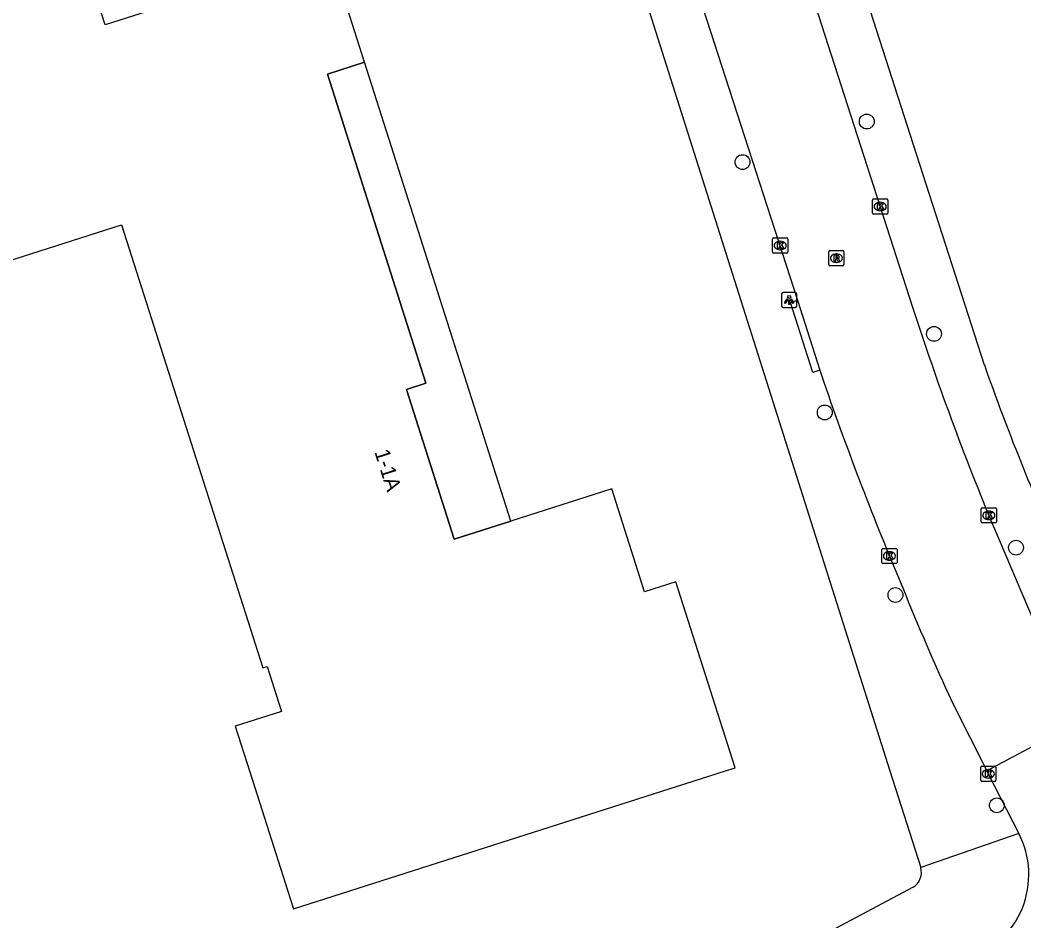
# Model space of a CAD drawing. Extents: x 159503 to 160347, y 382525 to 383272.
# Drawn here: x 159706.3 to 159772.6, y 382740.1 to 382799.5 of the extents above; entities that cross this region are included whole.
import ezdxf

# ---------------------------------------------------------------- set-up
doc = ezdxf.new("R2010")
doc.units = 0
for name, color, linetype in [('IMGEO_Boom', 7, 'Continuous'), ('IMGEO_Kolk', 7, 'Continuous'), ('IMGEO_Lichtpunt', 7, 'Continuous'), ('IMGEO_Pand', 7, 'Continuous'), ('IMGEO_Pand_nummerreeks', 7, 'Continuous'), ('IMGEO_Pand_overbouw', 7, 'Continuous'), ('IMGEO_Rijbaan_lokaal_open', 7, 'Continuous'), ('IMGEO_Rioolput', 7, 'Continuous'), ('IMGEO_Voetpad_open', 7, 'Continuous')]:
    doc.layers.add(name, color=color, linetype=linetype)

msp = doc.modelspace()

# ---------------------------------------------------------------- linework, layer by layer
at = {"layer": 'IMGEO_Boom'}
for centre in [(159762.236, 382792.834), (159754.031, 382790.155), (159766.672, 382778.825), (159759.463, 382773.639), (159772.085, 382764.721), (159764.125, 382761.599), (159770.819, 382747.721)]:
    msp.add_circle(centre, 0.489, dxfattribs=at)
at = {"layer": 'IMGEO_Kolk'}
for p, q in [((159762.618, 382786.797), (159762.618, 382787.649)), ((159762.693, 382787.723), (159763.545, 382787.723)), ((159763.106, 382787.503), (159763.131, 382787.503)), ((159763.619, 382787.649), (159763.619, 382786.797)), ((159763.545, 382786.723), (159762.693, 382786.723)), ((159763.129, 382786.943), (159763.104, 382786.943)), ((159756.016, 382784.226), (159756.016, 382785.078)), ((159756.091, 382785.152), (159756.943, 382785.152)), ((159756.504, 382784.932), (159756.529, 382784.932)), ((159757.017, 382785.078), (159757.017, 382784.226)), ((159756.943, 382784.152), (159756.091, 382784.152)), ((159756.527, 382784.372), (159756.502, 382784.372)), ((159769.793, 382766.426), (159769.793, 382767.278)), ((159769.868, 382767.352), (159770.72, 382767.352)), ((159770.281, 382767.132), (159770.306, 382767.132)), ((159770.794, 382767.278), (159770.794, 382766.426)), ((159770.72, 382766.352), (159769.868, 382766.352)), ((159770.304, 382766.572), (159770.279, 382766.572)), ((159763.23, 382763.747), (159763.23, 382764.599)), ((159763.305, 382764.673), (159764.157, 382764.673)), ((159763.718, 382764.453), (159763.743, 382764.453)), ((159764.231, 382764.599), (159764.231, 382763.747)), ((159764.157, 382763.673), (159763.305, 382763.673)), ((159763.741, 382763.893), (159763.716, 382763.893)), ((159769.755, 382749.379), (159769.755, 382750.231)), ((159769.83, 382750.305), (159770.682, 382750.305)), ((159770.756, 382750.231), (159770.756, 382749.379)), ((159770.266, 382749.525), (159770.241, 382749.525)), ((159770.243, 382750.085), (159770.268, 382750.085)), ((159770.682, 382749.305), (159769.83, 382749.305))]:
    msp.add_line(p, q, dxfattribs=at)
for points in [[(159762.618, 382786.797), (159762.618, 382787.649)], [(159762.693, 382787.723), (159763.545, 382787.723)], [(159762.939, 382787.423), (159763.062, 382787.423), (159763.062, 382787.272), (159763.192, 382787.423), (159763.356, 382787.423), (159763.21, 382787.272), (159763.363, 382787.023), (159763.211, 382787.023), (159763.126, 382787.187), (159763.062, 382787.12), (159763.062, 382787.023), (159762.939, 382787.023), (159762.939, 382787.423)], [(159763.619, 382787.649), (159763.619, 382786.797)], [(159763.545, 382786.723), (159762.693, 382786.723)], [(159756.016, 382784.226), (159756.016, 382785.078)], [(159756.091, 382785.152), (159756.943, 382785.152)], [(159756.337, 382784.852), (159756.46, 382784.852), (159756.46, 382784.701), (159756.59, 382784.852), (159756.754, 382784.852), (159756.608, 382784.701), (159756.761, 382784.452), (159756.609, 382784.452), (159756.524, 382784.616), (159756.46, 382784.549), (159756.46, 382784.452), (159756.337, 382784.452), (159756.337, 382784.852)], [(159757.017, 382785.078), (159757.017, 382784.226)], [(159756.943, 382784.152), (159756.091, 382784.152)], [(159769.793, 382766.426), (159769.793, 382767.278)], [(159769.868, 382767.352), (159770.72, 382767.352)], [(159770.114, 382767.052), (159770.237, 382767.052), (159770.237, 382766.901), (159770.367, 382767.052), (159770.531, 382767.052), (159770.385, 382766.901), (159770.538, 382766.652), (159770.386, 382766.652), (159770.301, 382766.816), (159770.237, 382766.749), (159770.237, 382766.652), (159770.114, 382766.652), (159770.114, 382767.052)], [(159770.794, 382767.278), (159770.794, 382766.426)], [(159770.72, 382766.352), (159769.868, 382766.352)], [(159763.23, 382763.747), (159763.23, 382764.599)], [(159763.305, 382764.673), (159764.157, 382764.673)], [(159763.551, 382764.373), (159763.674, 382764.373), (159763.674, 382764.222), (159763.804, 382764.373), (159763.968, 382764.373), (159763.822, 382764.222), (159763.975, 382763.973), (159763.823, 382763.973), (159763.738, 382764.137), (159763.674, 382764.07), (159763.674, 382763.973), (159763.551, 382763.973), (159763.551, 382764.373)], [(159764.231, 382764.599), (159764.231, 382763.747)], [(159764.157, 382763.673), (159763.305, 382763.673)], [(159769.755, 382749.379), (159769.755, 382750.231)], [(159769.83, 382750.305), (159770.682, 382750.305)], [(159770.756, 382750.231), (159770.756, 382749.379)], [(159770.076, 382750.005), (159770.199, 382750.005), (159770.199, 382749.854), (159770.329, 382750.005), (159770.493, 382750.005), (159770.347, 382749.854), (159770.5, 382749.605), (159770.348, 382749.605), (159770.263, 382749.769), (159770.199, 382749.702), (159770.199, 382749.605), (159770.076, 382749.605), (159770.076, 382750.005)], [(159770.682, 382749.305), (159769.83, 382749.305)]]:
    msp.add_lwpolyline(points, dxfattribs=at)
for centre, start, end in [((159762.695, 382787.647), 91.55205, 178.44795), ((159762.695, 382787.647), 91.55205, 178.44795), ((159763.543, 382787.647), 1.55205, 88.44795), ((159763.543, 382787.647), 1.55205, 88.44795), ((159762.695, 382786.799), 181.55205, 268.44795), ((159762.695, 382786.799), 181.55205, 268.44795), ((159763.543, 382786.799), 271.55205, 358.44795), ((159763.543, 382786.799), 271.55205, 358.44795), ((159756.093, 382785.076), 91.55205, 178.44795), ((159756.093, 382785.076), 91.55205, 178.44795), ((159756.941, 382785.076), 1.55205, 88.44795), ((159756.941, 382785.076), 1.55205, 88.44795), ((159756.093, 382784.228), 181.55205, 268.44795), ((159756.093, 382784.228), 181.55205, 268.44795), ((159756.941, 382784.228), 271.55205, 358.44795), ((159756.941, 382784.228), 271.55205, 358.44795), ((159769.87, 382767.276), 91.55205, 178.44795), ((159769.87, 382767.276), 91.55205, 178.44795), ((159770.718, 382767.276), 1.55205, 88.44795), ((159770.718, 382767.276), 1.55205, 88.44795), ((159769.87, 382766.428), 181.55205, 268.44795), ((159769.87, 382766.428), 181.55205, 268.44795), ((159770.718, 382766.428), 271.55205, 358.44795), ((159770.718, 382766.428), 271.55205, 358.44795), ((159763.307, 382764.597), 91.55205, 178.44795), ((159763.307, 382764.597), 91.55205, 178.44795), ((159764.155, 382764.597), 1.55205, 88.44795), ((159764.155, 382764.597), 1.55205, 88.44795), ((159763.307, 382763.749), 181.55205, 268.44795), ((159763.307, 382763.749), 181.55205, 268.44795), ((159764.155, 382763.749), 271.55205, 358.44795), ((159764.155, 382763.749), 271.55205, 358.44795), ((159769.832, 382750.229), 91.55205, 178.44795), ((159769.832, 382750.229), 91.55205, 178.44795), ((159770.68, 382750.229), 1.55205, 88.44795), ((159770.68, 382750.229), 1.55205, 88.44795), ((159769.832, 382749.381), 181.55205, 268.44795), ((159769.832, 382749.381), 181.55205, 268.44795), ((159770.68, 382749.381), 271.55205, 358.44795), ((159770.68, 382749.381), 271.55205, 358.44795)]:
    msp.add_arc(centre, 0.0765, start, end, dxfattribs=at)
for centre, major_axis, ratio, start_param, end_param in [((159763.105, 382787.223), (-0.387, 0.002), 0.722429, 4.712389, 7.853982), ((159763.13, 382787.223), (-0.39, 0.002), 0.717154, 1.570796, 4.712389), ((159756.503, 382784.652), (-0.387, 0.002), 0.722429, 4.712389, 7.853982), ((159756.528, 382784.652), (-0.39, 0.002), 0.717154, 1.570796, 4.712389), ((159770.28, 382766.852), (-0.387, 0.002), 0.722429, 4.712389, 7.853982), ((159770.305, 382766.852), (-0.39, 0.002), 0.717154, 1.570796, 4.712389), ((159763.717, 382764.173), (-0.387, 0.002), 0.722429, 4.712389, 7.853982), ((159763.742, 382764.173), (-0.39, 0.002), 0.717154, 1.570796, 4.712389), ((159770.242, 382749.805), (-0.387, 0.002), 0.722429, 4.712389, 7.853982), ((159770.267, 382749.805), (-0.39, 0.002), 0.717154, 1.570796, 4.712389)]:
    msp.add_ellipse(centre, major_axis=major_axis, ratio=ratio, start_param=start_param, end_param=end_param, dxfattribs=at)
at = {"layer": 'IMGEO_Lichtpunt'}
for p, q in [((159756.612, 382781.464), (159756.612, 382780.657)), ((159756.612, 382781.464), (159756.612, 382780.657)), ((159757.514, 382781.559), (159756.706, 382781.559)), ((159757.514, 382781.559), (159756.706, 382781.559)), ((159757.608, 382780.657), (159757.608, 382781.464)), ((159757.608, 382780.657), (159757.608, 382781.464)), ((159756.706, 382780.563), (159757.514, 382780.563)), ((159756.706, 382780.563), (159757.514, 382780.563))]:
    msp.add_line(p, q, dxfattribs=at)
for points in [[(159756.986, 382781.128), (159757.025, 382781.1), (159756.837, 382780.838), (159756.799, 382780.865), (159756.986, 382781.128)], [(159757.088, 382781.08), (159757.135, 382781.08), (159757.135, 382780.758), (159757.088, 382780.758), (159757.088, 382781.08)], [(159757.198, 382781.1), (159757.236, 382781.127), (159757.423, 382780.865), (159757.384, 382780.837), (159757.198, 382781.1)]]:
    msp.add_lwpolyline(points, dxfattribs=at)
msp.add_circle((159757.111, 382781.262), 0.0994, dxfattribs=at)
for centre, start, end in [((159756.706, 382781.464), 90, 180), ((159756.706, 382781.464), 90, 180), ((159757.514, 382781.464), 0, 90), ((159757.514, 382781.464), 0, 90), ((159756.706, 382780.657), 180, 270), ((159756.706, 382780.657), 180, 270), ((159757.514, 382780.657), 270, 0), ((159757.514, 382780.657), 270, 360)]:
    msp.add_arc(centre, 0.0946, start, end, dxfattribs=at)
at = {"layer": 'IMGEO_Pand'}
for points in [[(159726.63, 382795.959), (159729.084, 382796.741), (159726.792, 382803.935), (159711.953, 382799.207), (159710.531, 382803.67)], [(159705.767, 382802.152), (159682.294, 382794.673), (159687.633, 382777.914), (159713.049, 382786.012), (159722.358, 382756.794), (159722.657, 382756.889), (159723.605, 382753.912), (159720.541, 382752.936), (159721.48, 382750), (159722.471, 382746.901), (159723.999, 382742.131), (159724.396, 382740.892), (159752.918, 382750), (159753.541, 382750.199), (159749.635, 382762.458), (159747.561, 382761.797), (159745.396, 382768.592), (159738.73, 382766.468), (159735.002, 382765.28), (159731.853, 382775.164), (159733.127, 382775.57), (159726.63, 382795.959)]]:
    msp.add_lwpolyline(points, dxfattribs=at)
at = {"layer": 'IMGEO_Pand_overbouw'}
msp.add_lwpolyline([(159729.084, 382796.741), (159726.63, 382795.959), (159733.127, 382775.57), (159731.853, 382775.164), (159735.002, 382765.28), (159738.73, 382766.468)], close=True, dxfattribs=at)
at = {"layer": 'IMGEO_Rijbaan_lokaal_open'}
for points in [[(159745.694, 382841.502), (159751.166, 382824.443), (159759.246, 382799.219), (159765.262, 382780.583)], [(159748.293, 382809.925), (159749.144, 382807.34), (159757.672, 382781.038)], [(159757.672, 382781.038), (159759.144, 382776.429)], [(159759.144, 382776.429), (159759.398, 382775.632)], [(159770.662, 382765.962), (159773.966, 382758.2), (159776.407, 382753.325)], [(159767.87, 382754.536), (159770.155, 382750)], [(159776.407, 382753.325), (159770.155, 382750)], [(159770.155, 382750), (159770.257, 382749.806), (159772.274, 382745.86)]]:
    msp.add_lwpolyline(points, dxfattribs=at)
for centre, radius, start, end in [((159941.541, 382837.381), 185.203, 197.85913, 202.68245), ((159963.037, 382846.092), 215.484, 199.08578, 202.95246), ((159912.115, 382821.444), 159.007, 201.92959, 204.88419), ((159767.006, 382743.151), 5.924, 289.13916, 27.21521)]:
    msp.add_arc(centre, radius, start, end, dxfattribs=at)
at = {"layer": 'IMGEO_Rioolput'}
for p, q in [((159759.729, 382783.392), (159759.729, 382784.244)), ((159759.804, 382784.318), (159760.656, 382784.318)), ((159760.217, 382784.098), (159760.242, 382784.098)), ((159760.73, 382784.244), (159760.73, 382783.392)), ((159760.656, 382783.318), (159759.804, 382783.318)), ((159760.24, 382783.538), (159760.215, 382783.538))]:
    msp.add_line(p, q, dxfattribs=at)
for points in [[(159759.729, 382783.392), (159759.729, 382784.244)], [(159759.804, 382784.318), (159760.656, 382784.318)], [(159760.318, 382784.016), (159760.066, 382784.018), (159760.066, 382783.618)], [(159760.244, 382783.937), (159760.19, 382783.937), (159760.19, 382783.856)], [(159760.73, 382784.244), (159760.73, 382783.392)], [(159760.656, 382783.318), (159759.804, 382783.318)], [(159760.066, 382783.618), (159760.19, 382783.618), (159760.19, 382783.78), (159760.201, 382783.78)], [(159760.19, 382783.856), (159760.242, 382783.856)], [(159760.248, 382783.751), (159760.319, 382783.618), (159760.459, 382783.618), (159760.394, 382783.744)]]:
    msp.add_lwpolyline(points, dxfattribs=at)
for centre, radius, start, end in [((159759.806, 382784.242), 0.0765, 91.55205, 178.44795), ((159759.806, 382784.242), 0.0765, 91.55205, 178.44795), ((159760.25, 382783.841), 0.0964, 77.00612, 93.18647), ((159760.317, 382783.906), 0.109, 350.36119, 89.41601), ((159760.654, 382784.242), 0.0765, 1.55205, 88.44795), ((159760.654, 382784.242), 0.0765, 1.55205, 88.44795), ((159759.806, 382783.394), 0.0765, 181.55205, 268.44795), ((159759.806, 382783.394), 0.0765, 181.55205, 268.44795), ((159760.2, 382783.727), 0.0533, 26.02933, 88.69889), ((159760.226, 382784.045), 0.19, 274.7715, 282.96867), ((159760.264, 382783.898), 0.0378, 276.66336, 79.67722), ((159760.315, 382783.906), 0.112, 277.58423, 350.98172), ((159760.299, 382783.691), 0.108, 29.51342, 73.79051), ((159760.654, 382783.394), 0.0765, 271.55205, 358.44795), ((159760.654, 382783.394), 0.0765, 271.55205, 358.44795)]:
    msp.add_arc(centre, radius, start, end, dxfattribs=at)
for centre, major_axis, ratio, start_param, end_param in [((159760.216, 382783.818), (-0.387, 0.002), 0.722429, 4.712389, 7.853982), ((159760.241, 382783.818), (-0.39, 0.002), 0.717154, 1.570796, 4.712389)]:
    msp.add_ellipse(centre, major_axis=major_axis, ratio=ratio, start_param=start_param, end_param=end_param, dxfattribs=at)
at = {"layer": 'IMGEO_Voetpad_open'}
for points in [[(159742.845, 382815.409), (159744.764, 382809.45), (159747.728, 382800.527), (159763.767, 382750), (159765.793, 382743.617)], [(159769.997, 382776.771), (159765.523, 382790.674), (159760.683, 382805.736)], [(159759.144, 382776.429), (159758.667, 382776.281), (159757.195, 382780.89), (159757.672, 382781.038)], [(159772.274, 382745.86), (159765.793, 382743.617)], [(159765.3, 382742.325), (159754.381, 382736.516)]]:
    msp.add_lwpolyline(points, dxfattribs=at)
for centre, radius, start, end in [((159919.346, 382829.27), 158.307, 199.36758, 204.26043), ((159764.724, 382743.285), 1.119, 300.96042, 17.26798)]:
    msp.add_arc(centre, radius, start, end, dxfattribs=at)

# ---------------------------------------------------------------- texts
at = {"layer": 'IMGEO_Pand_nummerreeks'}
msp.add_text('1-1A', height=1, rotation=287.66981, dxfattribs=at).set_placement((159729.725, 382771.038))

doc.saveas('drawing.dxf')
